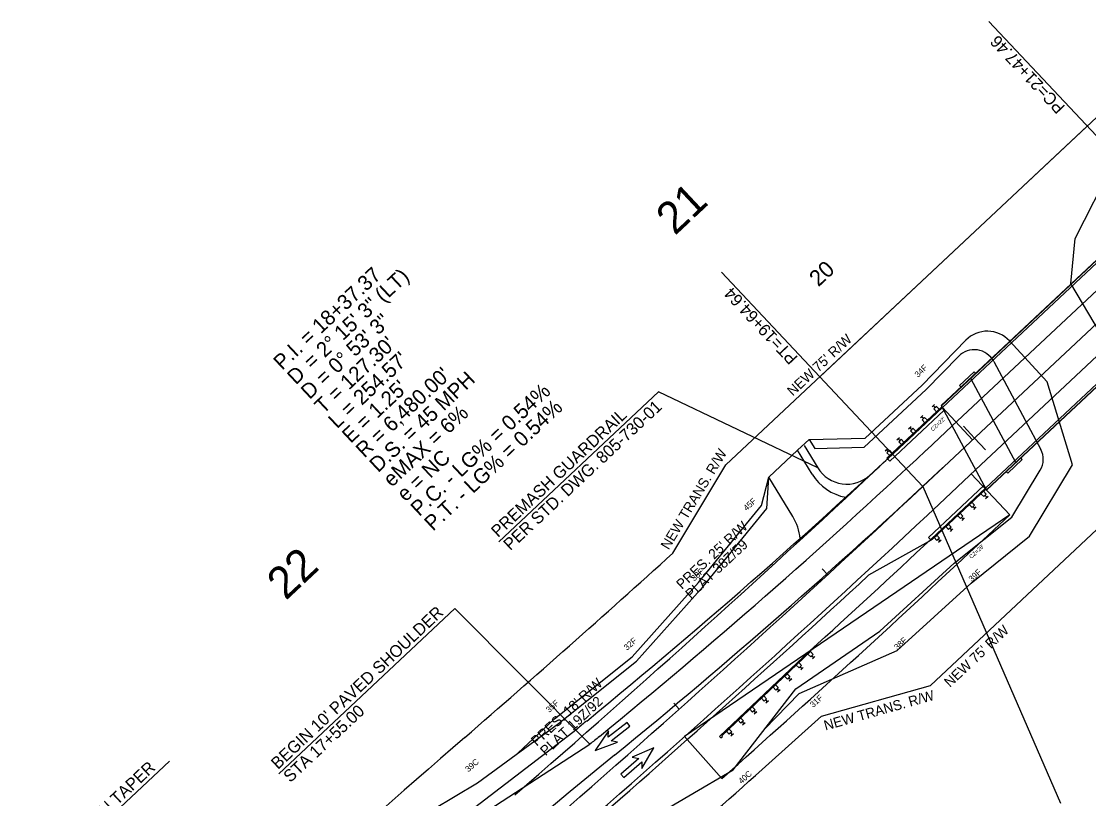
# Model space of a CAD drawing. Extents: x 1623239 to 1625698, y 1118659 to 1120751.
# Drawn here: x 1623885 to 1624417, y 1119413 to 1119800 of the extents above; entities that cross this region are included whole.
import ezdxf

# ---------------------------------------------------------------- set-up
doc = ezdxf.new("R2010")
doc.units = 0
for name, color, linetype in [('BR_CONCRETE', 7, 'Continuous'), ('BR_PROPOSED_TRAVELWAY', 7, 'Continuous'), ('Default', 7, 'Continuous'), ('RD_EX_DV_TX_Prop', 7, 'Continuous'), ('RD_EX_RW_TX', 7, 'Continuous'), ('RD_HC_CL_Rel', 7, 'Continuous'), ('RD_HC_Data', 7, 'Continuous'), ('RD_HC_Data_Tic', 7, 'Continuous'), ('RD_HC_TX_Sta50', 7, 'Continuous'), ('RD_PD_BOC', 7, 'Continuous'), ('RD_PD_CstnLmt', 7, 'Continuous'), ('RD_PD_CstnLmt_TX', 7, 'Continuous'), ('RD_PD_DR_ErosCtrl', 7, 'Continuous'), ('RD_PD_Driveway', 7, 'Continuous'), ('RD_PD_Final_TrvlWay', 7, 'Continuous'), ('RD_PD_Final_TX', 7, 'Continuous'), ('RD_PD_GR', 7, 'Continuous'), ('RD_PD_PaintMed', 7, 'Continuous'), ('RD_PD_PaveShd', 7, 'Continuous'), ('RD_PD_RW', 7, 'Continuous'), ('RD_PD_RW_TX', 7, 'Continuous'), ('RD_Sketch8', 7, 'Continuous')]:
    doc.layers.add(name, color=color, linetype=linetype)

# ---------------------------------------------------------------- blocks, each defined once
blk = doc.blocks.new('Guardrail_MTBBC3_Transition')
at = {"layer": 'RD_PD_GR'}
for p, q in [((37, 0.5), (0, 0.5)), ((0, 0.5), (0, 0)), ((0, 0), (37, 0)), ((3.525, 3.75), (1.775, 3.75)), ((1.775, 0.5), (1.775, 2.5)), ((1.775, 2.5), (3.525, 2.5)), ((3.525, 0.5), (1.775, 0.5)), ((2.65, 2.5), (2.65, 3.75)), ((3.525, 2.5), (3.525, 0.5)), ((11.525, 3.75), (9.775, 3.75)), ((9.775, 0.5), (9.775, 2.5)), ((9.775, 2.5), (11.525, 2.5)), ((11.525, 0.5), (9.775, 0.5)), ((10.65, 2.5), (10.65, 3.75)), ((11.525, 2.5), (11.525, 0.5)), ((19.525, 3.75), (17.775, 3.75)), ((17.775, 0.5), (17.775, 2.5)), ((17.775, 2.5), (19.525, 2.5)), ((19.525, 0.5), (17.775, 0.5)), ((18.65, 2.5), (18.65, 3.75)), ((19.525, 2.5), (19.525, 0.5)), ((27.525, 3.75), (25.775, 3.75)), ((25.775, 0.5), (25.775, 2.5)), ((25.775, 2.5), (27.525, 2.5)), ((27.525, 0.5), (25.775, 0.5)), ((26.65, 2.5), (26.65, 3.75)), ((27.525, 2.5), (27.525, 0.5)), ((30.65, 0.5), (30.65, 0)), ((35.525, 3.75), (33.775, 3.75)), ((33.775, 0.5), (33.775, 2.5)), ((33.775, 2.5), (35.525, 2.5)), ((35.525, 0.5), (33.775, 0.5)), ((34.65, 2.5), (34.65, 3.75)), ((35.525, 2.5), (35.525, 0.5)), ((37, 0), (37, 0.5))]:
    blk.add_line(p, q, dxfattribs=at)

msp = doc.modelspace()

# ---------------------------------------------------------------- linework, layer by layer
at = {"layer": 'BR_CONCRETE'}
for p, q in [((1624343.39, 1119608.68), (1624449.15, 1119707.87)), ((1624343.45, 1119608.57), (1624449.22, 1119707.76)), ((1624343.94, 1119607.65), (1624449.7, 1119706.85)), ((1624365.44, 1119567.5), (1624471.2, 1119666.69)), ((1624365.93, 1119566.58), (1624471.69, 1119665.77)), ((1624365.99, 1119566.47), (1624471.75, 1119665.66)), ((1624357.98, 1119622.36), (1624380.58, 1119580.15)), ((1624343.39, 1119608.68), (1624365.99, 1119566.47))]:
    msp.add_line(p, q, dxfattribs=at)
for points in [[(1624360.53, 1119624.76), (1624359.85, 1119625.49), (1624352.55, 1119618.65), (1624353.24, 1119617.92)], [(1624383.81, 1119581.82), (1624383.13, 1119582.55), (1624375.84, 1119575.71), (1624376.52, 1119574.98)]]:
    msp.add_lwpolyline(points, close=True, dxfattribs=at)
at = {"layer": 'BR_PROPOSED_TRAVELWAY'}
for p, q in [((1624348.83, 1119598.53), (1624454.59, 1119697.72)), ((1624360.55, 1119576.62), (1624466.32, 1119675.81))]:
    msp.add_line(p, q, dxfattribs=at)
at = {"layer": 'Default'}
msp.add_line((1624365.44, 1119567.5), (1624471.2, 1119666.69), dxfattribs=at)
at = {"layer": 'RD_HC_CL_Rel'}
msp.add_line((1624334.12, 1119568.29), (1624467.48, 1119693.35), dxfattribs=at)
msp.add_arc((1619901.34, 1124294.89), 6480, 310.911734, 313.16267, dxfattribs=at)
at = {"layer": 'RD_HC_Data'}
for p, q in [((1624467.48, 1119693.35), (1624367.16, 1119800.32)), ((1624334.12, 1119568.29), (1624233.81, 1119675.25))]:
    msp.add_line(p, q, dxfattribs=at)
at = {"layer": 'RD_HC_Data_Tic'}
for p, q in [((1624359.92, 1119592.48), (1624354.45, 1119598.32)), ((1624365.39, 1119586.64), (1624359.92, 1119592.48)), ((1624286.76, 1119524.31), (1624284.05, 1119527.25)), ((1624212.62, 1119457.2), (1624209.96, 1119460.19))]:
    msp.add_line(p, q, dxfattribs=at)
at = {"layer": 'RD_PD_BOC'}
for p, q in [((1624343.7, 1119608.11), (1624316.31, 1119582.43)), ((1624317.68, 1119580.97), (1624344.67, 1119606.29)), ((1624317.68, 1119580.97), (1624316.31, 1119582.43)), ((1624364.71, 1119568.86), (1624337.03, 1119542.91)), ((1624365.78, 1119567.13), (1624338.4, 1119541.45)), ((1624365.78, 1119567.13), (1624350.19, 1119552.51)), ((1624337.03, 1119542.91), (1624338.4, 1119541.45))]:
    msp.add_line(p, q, dxfattribs=at)
at = {"layer": 'RD_PD_CstnLmt'}
for p, q in [((1624335.86, 1119616.71), (1624351.98, 1119633.19)), ((1624369.55, 1119630.69), (1624393.06, 1119586.77)), ((1624304.86, 1119587.92), (1624335.86, 1119616.71)), ((1624271.74, 1119586.38), (1624277.51, 1119591.8)), ((1624277.51, 1119591.8), (1624280.25, 1119587.32)), ((1624280.25, 1119587.32), (1624304.86, 1119587.92)), ((1624256.38, 1119557.36), (1624257.39, 1119572.9)), ((1624378.62, 1119553), (1624392.79, 1119576.38)), ((1624224.57, 1119518.5), (1624256.38, 1119557.36)), ((1624349.81, 1119530.04), (1624378.62, 1119553)), ((1624312.7, 1119496.09), (1624349.81, 1119530.04)), ((1624191.3, 1119481.12), (1624224.57, 1119518.5)), ((1624270.77, 1119467.46), (1624312.7, 1119496.09)), ((1624152.39, 1119450.03), (1624191.3, 1119481.12)), ((1624239.51, 1119427.03), (1624270.77, 1119467.46)), ((1624112.11, 1119420.41), (1624152.39, 1119450.03)), ((1624195.36, 1119401.06), (1624239.51, 1119427.03)), ((1624068.03, 1119394.33), (1624112.11, 1119420.41))]:
    msp.add_line(p, q, dxfattribs=at)
for centre, radius, start, end in [((1624359.85, 1119625.49), 11.01, 28.1627, 135.6281), ((1624383.81, 1119581.82), 10.49, 328.7908, 28.1627)]:
    msp.add_arc(centre, radius, start, end, dxfattribs=at)
at = {"layer": 'RD_PD_DR_ErosCtrl'}
for p, q in [((1624410.22, 1119692.05), (1624429.09, 1119729.26)), ((1624408.1, 1119669.48), (1624410.22, 1119692.05)), ((1624422.77, 1119644.63), (1624408.1, 1119669.48)), ((1624333.81, 1119618.9), (1624355.67, 1119641.25)), ((1624396.28, 1119620.47), (1624377.42, 1119640.93)), ((1624408.9, 1119579.05), (1624396.28, 1119620.47)), ((1624305.36, 1119592.48), (1624333.81, 1119618.9)), ((1624277.51, 1119591.8), (1624305.36, 1119592.48)), ((1624387.43, 1119543.61), (1624408.9, 1119579.05)), ((1624253.65, 1119558.76), (1624257.39, 1119572.9)), ((1624222.29, 1119520.45), (1624253.65, 1119558.76)), ((1624358.26, 1119520.14), (1624387.43, 1119543.61)), ((1624189.23, 1119483.3), (1624222.29, 1119520.45)), ((1624321.47, 1119486.5), (1624358.26, 1119520.14)), ((1624150.52, 1119452.37), (1624189.23, 1119483.3)), ((1624272.46, 1119464.99), (1624321.47, 1119486.5)), ((1624255.14, 1119447.25), (1624272.46, 1119464.99)), ((1624132.25, 1119435.22), (1624150.52, 1119452.37))]:
    msp.add_line(p, q, dxfattribs=at)
msp.add_arc((1624366.39, 1119630.77), 15, 42.6666, 135.635, dxfattribs=at)
at = {"layer": 'RD_PD_Driveway'}
for p, q in [((1624257.39, 1119572.9), (1624271.74, 1119586.38)), ((1624279.03, 1119574.45), (1624271.74, 1119586.38)), ((1624269.37, 1119553.29), (1624257.39, 1119572.9))]:
    msp.add_line(p, q, dxfattribs=at)
for centre, start, end in [((1624300.36, 1119587.49), 211.4265, 259.3951), ((1624248.03, 1119540.26), 4.7417, 31.4265)]:
    msp.add_arc(centre, 25, start, end, dxfattribs=at)
at = {"layer": 'RD_PD_Final_TrvlWay'}
for p, q in [((1624335.95, 1119586.45), (1624348.83, 1119598.53)), ((1624342.33, 1119559.54), (1624360.55, 1119576.62)), ((1624083.51, 1119385), (1624168.16, 1119439.74))]:
    msp.add_line(p, q, dxfattribs=at)
for centre, radius, start, end in [((1622152.08, 1121915.07), 3192.45, 309.27048, 313.16267), ((1619901.34, 1124294.89), 6492, 310.911734, 313.16267), ((1628628.65, 1113993.92), 7039.39, 129.270481, 129.319806)]:
    msp.add_arc(centre, radius, start, end, dxfattribs=at)
at = {"layer": 'RD_PD_Final_TX'}
for p, q in [((1624122.68, 1119540.72), (1624202.38, 1119615.47)), ((1624281.79, 1119577.6), (1624202.38, 1119615.47)), ((1624334.12, 1119568.29), (1624402.92, 1119410.28)), ((1624012.9, 1119425), (1624100.74, 1119507.37)), ((1624168.16, 1119439.74), (1624100.74, 1119507.37)), ((1624186.71, 1119450.6), (1624177.27, 1119443.19)), ((1624188.1, 1119448.83), (1624186.71, 1119450.6)), ((1624177.35, 1119446.49), (1624170.77, 1119436.66)), ((1624177.27, 1119443.19), (1624177.35, 1119446.49)), ((1624178.66, 1119441.42), (1624188.1, 1119448.83)), ((1624170.77, 1119436.66), (1624181.89, 1119440.71)), ((1624181.89, 1119440.71), (1624178.66, 1119441.42)), ((1624200.06, 1119437.93), (1624189.2, 1119433.23)), ((1624194.07, 1119427.72), (1624200.06, 1119437.93)), ((1623888.54, 1119365.77), (1623958.44, 1119431.32)), ((1624192.47, 1119432.71), (1624183.48, 1119424.76)), ((1624184.97, 1119423.07), (1624193.96, 1119431.02)), ((1624189.2, 1119433.23), (1624192.47, 1119432.71)), ((1624193.96, 1119431.02), (1624194.07, 1119427.72)), ((1624183.48, 1119424.76), (1624184.97, 1119423.07))]:
    msp.add_line(p, q, dxfattribs=at)
at = {"layer": 'RD_PD_GR'}
for p, q in [((1624328.12, 1119593.5), (1624328.44, 1119593.12)), ((1624275.01, 1119588.69), (1624281.79, 1119577.6)), ((1624349.17, 1119552.23), (1624349.94, 1119552.96)), ((1624277.82, 1119486.29), (1624232.8, 1119443.66)), ((1624233.87, 1119443.98), (1624278.16, 1119485.93)), ((1624276.89, 1119484.73), (1624278.16, 1119485.93)), ((1624278.27, 1119483.27), (1624276.89, 1119484.73)), ((1624278.16, 1119485.93), (1624277.82, 1119486.29)), ((1624278.16, 1119485.93), (1624279.54, 1119484.48)), ((1624279.54, 1119484.48), (1624278.27, 1119483.27)), ((1624278.9, 1119483.88), (1624279.76, 1119482.97)), ((1624279.12, 1119482.37), (1624280.4, 1119483.57)), ((1624271.08, 1119479.23), (1624272.35, 1119480.43)), ((1624272.46, 1119477.77), (1624271.08, 1119479.23)), ((1624272.35, 1119480.43), (1624273.73, 1119478.98)), ((1624273.73, 1119478.98), (1624272.46, 1119477.77)), ((1624273.09, 1119478.37), (1624273.95, 1119477.47)), ((1624273.32, 1119476.87), (1624274.59, 1119478.07)), ((1624265.27, 1119473.72), (1624266.54, 1119474.93)), ((1624266.65, 1119472.27), (1624265.27, 1119473.72)), ((1624266.54, 1119474.93), (1624267.92, 1119473.48)), ((1624267.92, 1119473.48), (1624266.65, 1119472.27)), ((1624267.28, 1119472.87), (1624268.14, 1119471.97)), ((1624267.51, 1119471.36), (1624268.78, 1119472.57)), ((1624259.47, 1119468.22), (1624260.74, 1119469.43)), ((1624260.84, 1119466.77), (1624259.47, 1119468.22)), ((1624260.74, 1119469.43), (1624262.11, 1119467.97)), ((1624262.11, 1119467.97), (1624260.84, 1119466.77)), ((1624261.48, 1119467.37), (1624262.34, 1119466.46)), ((1624261.7, 1119465.86), (1624262.97, 1119467.07)), ((1624253.66, 1119462.72), (1624254.93, 1119463.92)), ((1624255.03, 1119461.27), (1624253.66, 1119462.72)), ((1624254.93, 1119463.92), (1624256.3, 1119462.47)), ((1624256.3, 1119462.47), (1624255.03, 1119461.27)), ((1624255.67, 1119461.87), (1624256.53, 1119460.96)), ((1624255.89, 1119460.36), (1624257.16, 1119461.57)), ((1624247.85, 1119457.22), (1624249.12, 1119458.42)), ((1624249.22, 1119455.77), (1624247.85, 1119457.22)), ((1624249.12, 1119458.42), (1624250.49, 1119456.97)), ((1624250.49, 1119456.97), (1624249.22, 1119455.77)), ((1624249.86, 1119456.37), (1624250.72, 1119455.46)), ((1624250.08, 1119454.86), (1624251.35, 1119456.06)), ((1624242.04, 1119451.72), (1624243.31, 1119452.92)), ((1624243.42, 1119450.27), (1624242.04, 1119451.72)), ((1624243.31, 1119452.92), (1624244.69, 1119451.47)), ((1624244.69, 1119451.47), (1624243.42, 1119450.27)), ((1624244.05, 1119450.87), (1624244.91, 1119449.96)), ((1624244.28, 1119449.36), (1624245.55, 1119450.56)), ((1624236.23, 1119446.22), (1624237.5, 1119447.42)), ((1624237.61, 1119444.77), (1624236.23, 1119446.22)), ((1624237.5, 1119447.42), (1624238.88, 1119445.97)), ((1624238.88, 1119445.97), (1624237.61, 1119444.77)), ((1624238.24, 1119445.37), (1624239.1, 1119444.46)), ((1624238.47, 1119443.86), (1624239.74, 1119445.06)), ((1624215.2, 1119443.71), (1624215.33, 1119443.55)), ((1624232.8, 1119443.66), (1624233.49, 1119442.93)), ((1624233.49, 1119442.93), (1624234.22, 1119443.62)), ((1624234.22, 1119443.62), (1624233.87, 1119443.98))]:
    msp.add_line(p, q, dxfattribs=at)
for centre, radius, start, end in [((1624296.3, 1119586.46), 17, 211.4265, 312.6393), ((1622152.08, 1121915.07), 3182.45, 312.63932, 312.86264), ((1619901.35, 1124294.88), 6502, 312.306434, 313.033119)]:
    msp.add_arc(centre, radius, start, end, dxfattribs=at)
at = {"layer": 'RD_PD_PaintMed'}
for centre, radius, start, end in [((1622152.08, 1121915.07), 3204.45, 309.27048, 313.16267), ((1628628.65, 1113993.92), 7027.39, 129.270481, 131.762152)]:
    msp.add_arc(centre, radius, start, end, dxfattribs=at)
at = {"layer": 'RD_PD_PaveShd'}
for p, q in [((1624338.4, 1119541.45), (1624307.09, 1119524)), ((1624082.22, 1119386.53), (1624161.82, 1119447.48))]:
    msp.add_line(p, q, dxfattribs=at)
for centre, radius, start, end in [((1622152.08, 1121915.07), 3182.45, 309.27048, 313.3941), ((1619901.34, 1124294.89), 6494, 310.911734, 312.721401), ((1628628.65, 1113993.92), 7049.39, 129.270481, 129.319806)]:
    msp.add_arc(centre, radius, start, end, dxfattribs=at)
at = {"layer": 'RD_PD_RW'}
for p, q in [((1624236, 1119579.09), (1624454.27, 1119783.79)), ((1624282.82, 1119623), (1624416.17, 1119748.06)), ((1624338, 1119469.11), (1624557.4, 1119674.87)), ((1624209.55, 1119535.1), (1624236, 1119579.09)), ((1624283.62, 1119453.77), (1624338, 1119469.11))]:
    msp.add_line(p, q, dxfattribs=at)
for centre, radius, start, end in [((1619901.34, 1124294.89), 6420, 310.911734, 312.149056), ((1619901.34, 1124294.89), 6530, 310.911734, 312.151971), ((1628388.79, 1114500.77), 6540, 130.911734, 133.16267)]:
    msp.add_arc(centre, radius, start, end, dxfattribs=at)
at = {"layer": 'RD_Sketch8'}
for p, q in [((1624324.54, 1119589.46), (1624343.94, 1119607.65)), ((1624358.99, 1119591.61), (1624343.94, 1119607.65)), ((1624358.39, 1119574.59), (1624377.54, 1119554.17)), ((1624377.54, 1119554.17), (1624215.33, 1119443.55)), ((1624361.49, 1119539.11), (1624377.54, 1119554.17)), ((1624215.33, 1119443.55), (1624233.94, 1119422.63))]:
    msp.add_line(p, q, dxfattribs=at)
for radius, start in [(6458, 310.911734), (6520, 311.644706)]:
    msp.add_arc((1619901.34, 1124294.89), radius, start, 313.16267, dxfattribs=at)

# ---------------------------------------------------------------- block references
at = {"layer": 'RD_PD_Final_TrvlWay', "yscale": -1, "rotation": -136.83733015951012}
msp.add_blockref('Guardrail_MTBBC3_Transition', (1624343.94, 1119607.65), dxfattribs=at)
at = {"layer": 'RD_PD_Final_TrvlWay', "rotation": -136.83733015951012}
msp.add_blockref('Guardrail_MTBBC3_Transition', (1624365.44, 1119567.5), dxfattribs=at)

# ---------------------------------------------------------------- texts
at = {"layer": 'RD_EX_DV_TX_Prop'}
for s, p in [('21', (1624210.5, 1119693.17)), ('22', (1624016.41, 1119511.15))]:
    msp.add_text(s, height=16, rotation=43.1627, dxfattribs=at).set_placement(p)
at = {"layer": 'RD_EX_RW_TX'}
for s, rotation, p in [("PRES. 25' R/W", 43.0092, (1624214.03, 1119516.73)), ('PLAT 38Z/59', 43.0092, (1624218.58, 1119511.85)), ("PRES. 18' R/W", 42.9276, (1624141.57, 1119438.54)), ('PLAT 19Z/92', 42.9276, (1624146.11, 1119433.65))]:
    msp.add_text(s, height=5, rotation=rotation, dxfattribs=at).set_placement(p)
at = {"layer": 'RD_HC_Data'}
for s, height, rotation, p in [('PC=21+47.46', 6, 133.1627, (1624405.54, 1119757.74)), ('P.I. = 18+37.37', 7.5, 43.1627, (1624014.59, 1119626.01)), ('    = 2%%d 15\' 3" (LT)', 7.5, 43.1627, (1624021.43, 1119618.72)), ('PT=19+64.64', 6, 133.1627, (1624272.19, 1119632.68)), ('D = 0%%d 53\' 3"', 7.5, 43.1627, (1624028.27, 1119611.42)), ("T = 127.30'", 7.5, 43.1627, (1624035.12, 1119604.13)), ("L = 254.57'", 7.5, 43.1627, (1624041.96, 1119596.83)), ('D', 7.5, 43.1627, (1624021.43, 1119618.72)), ("R = 6,480.00'", 7.5, 43.1627, (1624055.64, 1119582.24)), ('D.S. = 45 MPH', 7.5, 43.1627, (1624062.48, 1119574.95)), ("E = 1.25'", 7.5, 43.1627, (1624048.8, 1119589.54)), ('P.C. - LG% = 0.54%', 7.5, 43.1627, (1624083, 1119553.07)), ('P.T. - LG% = 0.54%', 7.5, 43.1627, (1624089.84, 1119545.77)), ('eMAX = 6%', 7.5, 43.1627, (1624069.32, 1119567.66)), ('e = NC', 7.5, 43.1627, (1624076.16, 1119560.36))]:
    msp.add_text(s, height=height, rotation=rotation, dxfattribs=at).set_placement(p)
at = {"layer": 'RD_HC_TX_Sta50'}
msp.add_text('20', height=8, rotation=42.9276, dxfattribs=at).set_placement((1624282.12, 1119667.61))
at = {"layer": 'RD_PD_CstnLmt_TX'}
for s, rotation, p in [('34F', 43.1627, (1624331.78, 1119622.48)), ('45F', 42.5912, (1624246.31, 1119555.93)), ('38F', 42.1491, (1624220.17, 1119520.86)), ('39F', 43.0333, (1624358.69, 1119520.53)), ('32F', 41.707, (1624186.65, 1119486.34)), ('38F', 42.5912, (1624321.5, 1119486.52)), ('35F', 41.2649, (1624147.78, 1119455.29)), ('31F', 42.1491, (1624279.49, 1119457.83)), ('39C', 41.0007, (1624107.51, 1119425.69)), ('40C', 41.707, (1624243.76, 1119419.73))]:
    msp.add_text(s, height=3, rotation=rotation, dxfattribs=at).set_placement(p)
at = {"layer": 'RD_PD_Final_TX'}
for s, p in [('PER STD. DWG. 805-730-01', (1624128.44, 1119536.04)), ('PREMASH GUARDRAIL', (1624122.28, 1119542.61)), ("BEGIN 10' PAVED SHOULDER", (1624012.51, 1119426.89)), ('STA 17+55.00', (1624018.66, 1119420.33)), ('BEGIN MEDIAN TAPER', (1623888.14, 1119367.66))]:
    msp.add_text(s, height=6, rotation=43.1625, dxfattribs=at).set_placement(p)
at = {"layer": 'RD_PD_RW'}
msp.add_text('NEW TRANS. R/W', height=5, rotation=58.9862, dxfattribs=at).set_placement((1624207.41, 1119536.38))
at = {"layer": 'RD_PD_RW_TX'}
for s, rotation, p in [("NEW 75' R/W", 43.1627, (1624269.36, 1119613.11)), ("NEW 75' R/W", 43.1627, (1624347.68, 1119467.89)), ('NEW TRANS. R/W', 15.7511, (1624285.65, 1119446.55))]:
    msp.add_text(s, height=5, rotation=rotation, dxfattribs=at).set_placement(p)
at = {"layer": 'RD_Sketch8'}
for s, rotation, p in [("CZ=22'", 43.3577, (1624339.22, 1119595.7)), ("CZ=28'", 43.1627, (1624358.44, 1119532.12))]:
    msp.add_text(s, height=2, rotation=rotation, dxfattribs=at).set_placement(p)

doc.saveas('drawing.dxf')
